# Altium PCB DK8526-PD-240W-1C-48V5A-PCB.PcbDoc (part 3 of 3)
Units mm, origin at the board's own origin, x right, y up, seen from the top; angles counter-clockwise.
Board outline 89.28 x 73.8 mm, 4 copper layers (Top Layer, Layer 1, Layer 2, Bottom Layer), stack 0.603 mm thick; 182 components, 162 nets, 518 pads, 506 vias.
Unrouted connection lines stored in the file: 4.
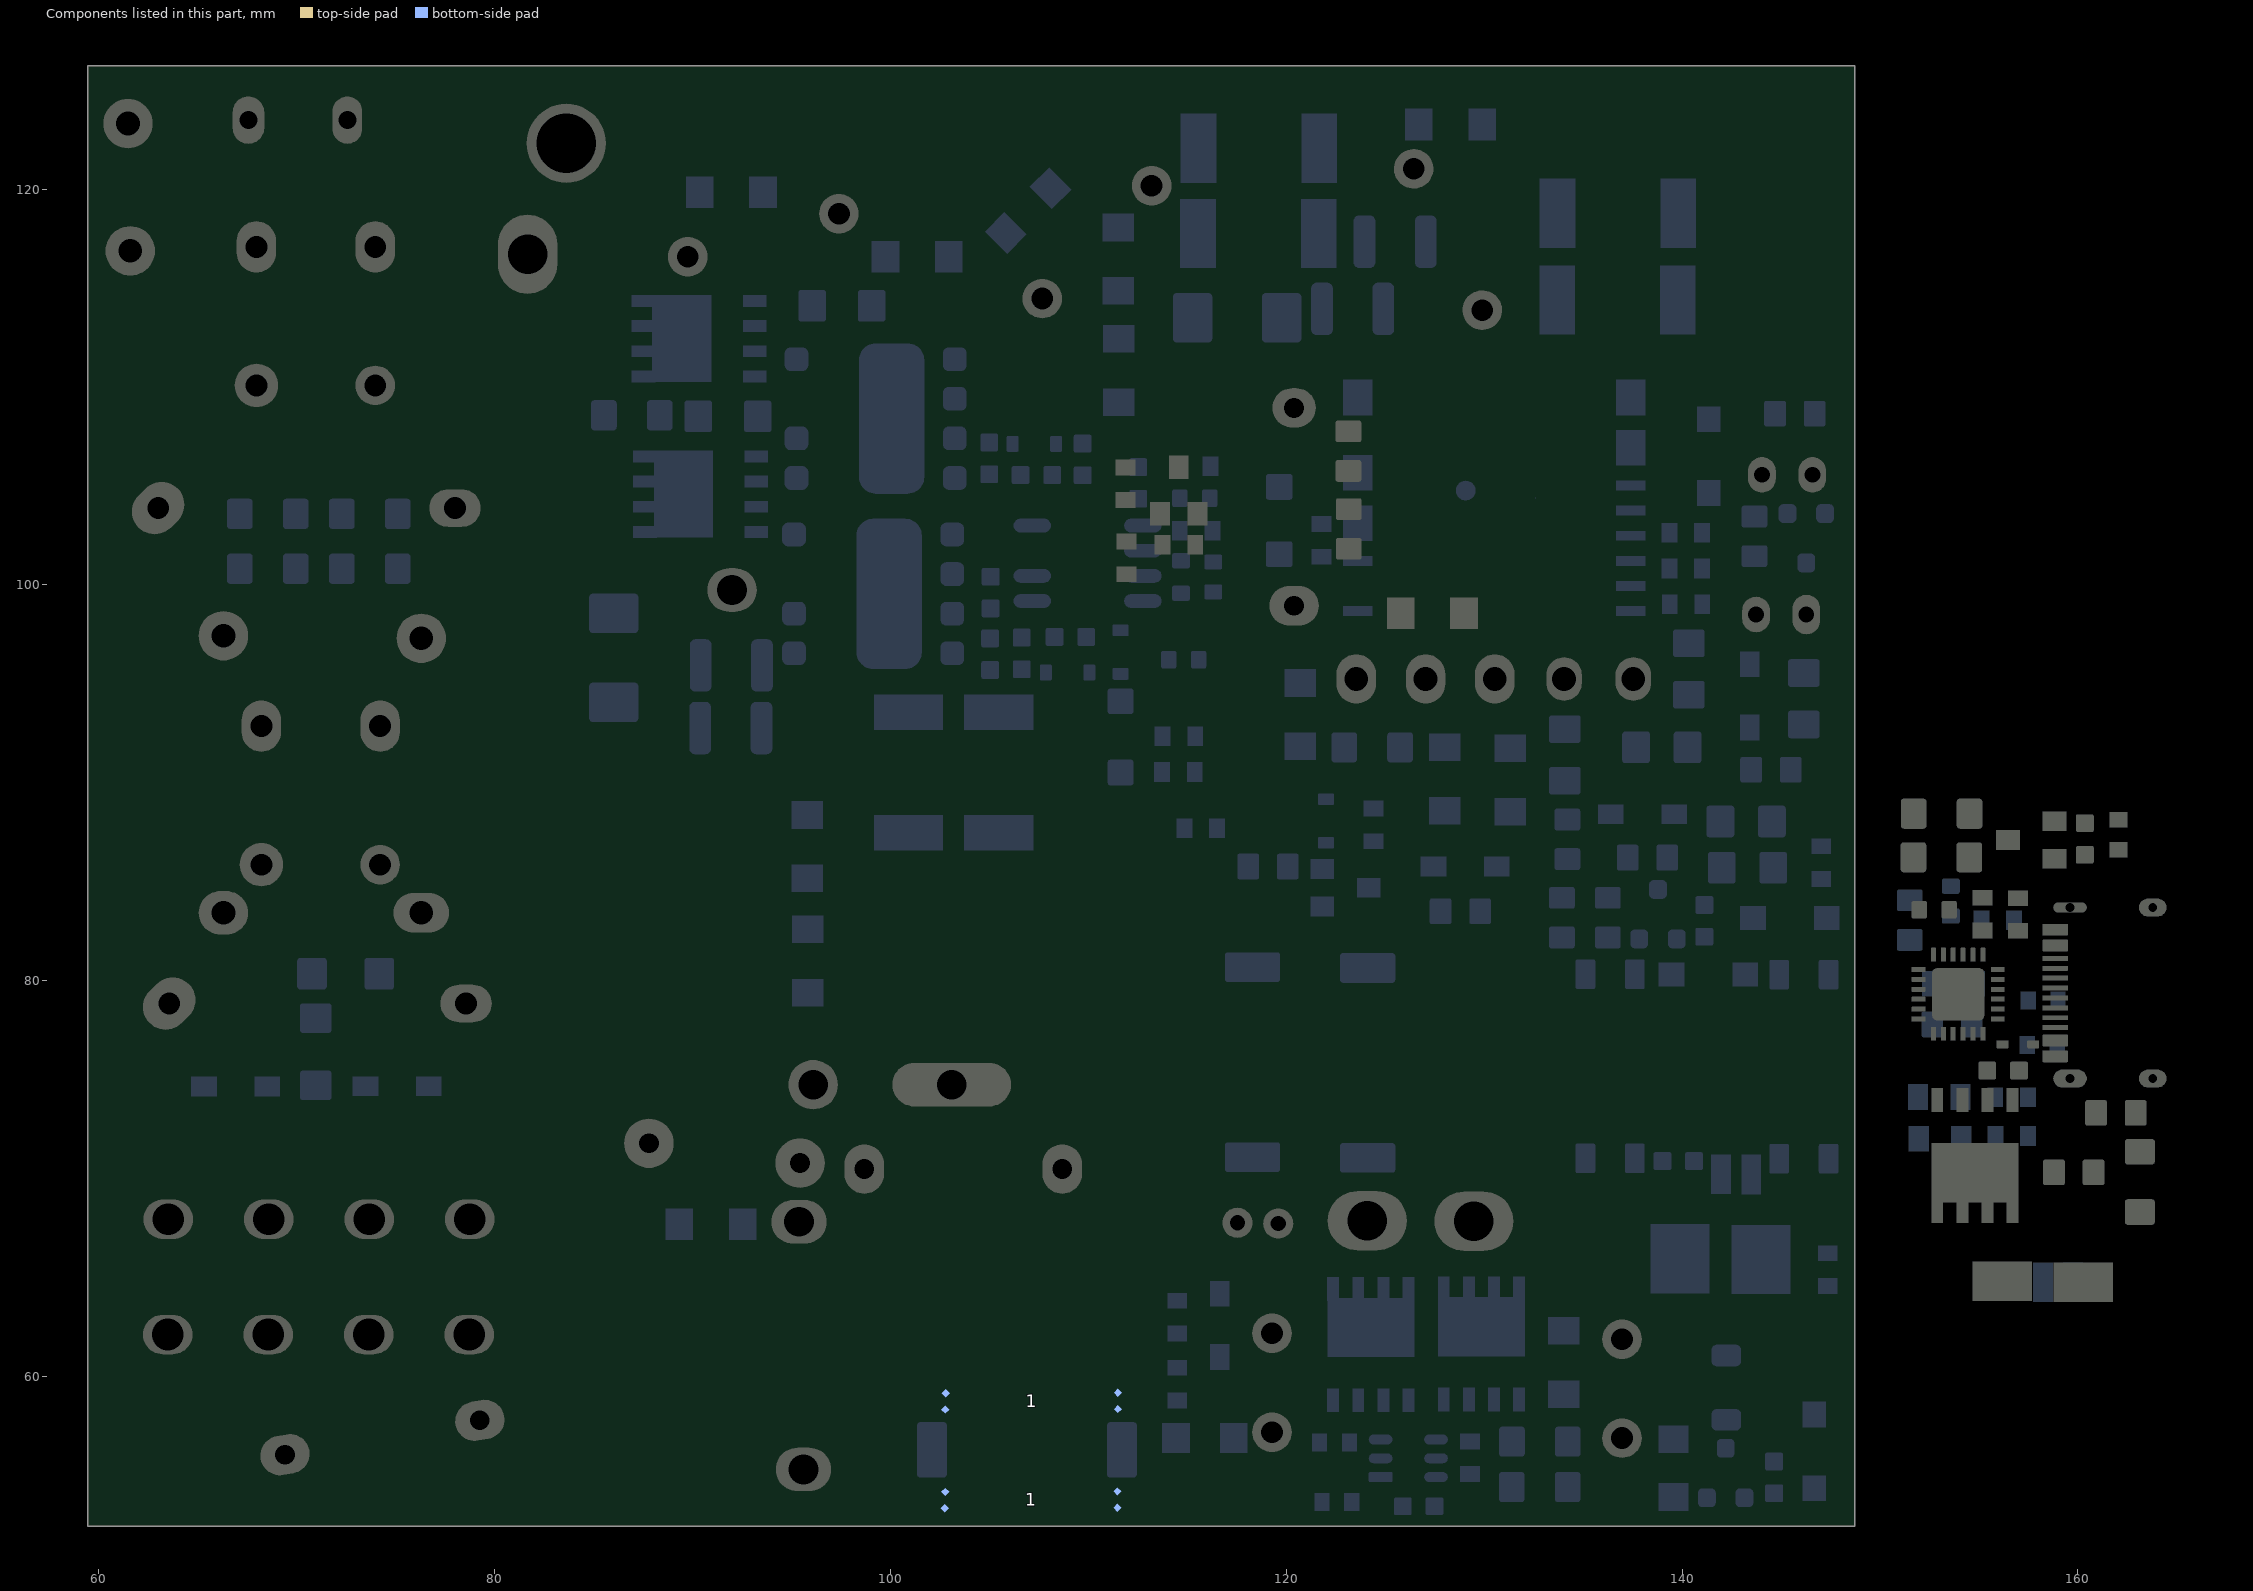
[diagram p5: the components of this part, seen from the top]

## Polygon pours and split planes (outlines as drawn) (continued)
300-R on Bottom Layer "NONET_L-01_P-001" (hatched Horizontal grid 0.2 track 0.2, pour order 442): 84.918,95.123 87.181,95.123 87.485,94.819 87.485,74.948 88.87,73.563 88.87,71.059 88.006,70.195 86.53,70.195 85.859,70.865 85.859,91.812 84.733,92.938 84.733,94.939
PGND on Bottom Layer "NONET_L-01_P-001" (hatched Horizontal grid 0.2 track 0.2, pour order 444): 131.773,107.101 131.773,111.059 132.039,111.325 135.577,111.325 136.506,112.254 136.58,112.18 136.58,109.136 135.732,108.288
PGND on Bottom Layer "NONET_L-01_P-001" (hatched Horizontal grid 0.2 track 0.2, pour order 449): 141.605,108.839 143.209,107.235 144.615,107.235 145.062,106.787 145.062,105.015 144.718,104.671 143.632,104.671 142.461,105.841 140.986,105.841
PGND on Bottom Layer "NONET_L-01_P-001" (hatched Horizontal grid 0.2 track 0.2, pour order 450): 147.955,99.568 146.027,99.568 145.571,99.112 145.571,97.988 146.026,97.533 147.907,97.533 148.109,97.735 148.109,99.414
GND on Bottom Layer "NONET_L-01_P-001" (hatched Horizontal grid 0.2 track 0.2, pour order 466): 92.583,89.281 89.67,89.281 89.133,88.744 89.133,77.315 90.039,76.409 91.961,76.409 92.937,77.385 92.937,88.927
PGND on Bottom Layer "NONET_L-01_P-001" (hatched Horizontal grid 0.2 track 0.2, pour order 470): 141.097,107.696 141.097,107.823 143.306,110.032 147.617,110.032 148.209,110.624 148.209,125.476 147.868,125.817 141.565,125.817 139.954,124.206 139.954,109.601
PGND on Bottom Layer "NONET_L-01_P-001" (hatched Horizontal grid 0.2 track 0.2, pour order 471): 18 vertices, not listed, extent 136.423,98.505 141.474,106.418
VS on Bottom Layer "NONET_L-01_P-001" (hatched Horizontal grid 0.2 track 0.2, pour order 477): 138.879,103.141 138.53,102.791 136.814,102.791 136.704,102.682 136.704,102.321 136.797,102.228 139.647,102.228 139.869,102.006 139.869,102.938 139.666,103.141
NetC22_2 on Bottom Layer "NONET_L-01_P-001" (hatched Horizontal grid 0.2 track 0.2, pour order 478): 136.719,101.075 136.716,101.079 136.716,101.416 136.844,101.544 139.473,101.544 139.662,101.355 139.662,100.377 139.618,100.333 139.113,100.333 138.504,100.941 136.821,100.941 136.718,101.044 136.718,101.077
VCC_EXT on Bottom Layer "NONET_L-01_P-001" (hatched Horizontal grid 0.2 track 0.2, pour order 479): 18 vertices, not listed, extent 136.661,98.452 139.704,100.314
GND on Bottom Layer "NONET_L-01_P-001" (hatched Horizontal grid 0.2 track 0.2, pour order 480): 85.181,125.766 85.598,125.349 85.598,117.856 82.423,114.681 80.899,114.681 80.01,115.57 80.01,125.086 80.69,125.766
d23 on Bottom Layer "NONET_L-01_P-001" (hatched Horizontal grid 0.2 track 0.2, pour order 481): 118.016,68.599 116.964,68.599 116.782,68.418 116.782,65.568 115.606,64.391 114.203,64.391 113.897,64.085 113.897,63.451 114.002,63.346 116.994,63.346 117.841,64.194 118.165,64.517 118.165,68.458 118.023,68.599
VCCF on Bottom Layer "NONET_L-01_P-001" (hatched Horizontal grid 0.2 track 0.2, pour order 482): 117.096,61.696 117.086,61.686 116.21,61.686 116.129,61.604 116.129,60.24 115.171,59.283 113.97,59.283 113.542,58.855 113.542,57.163 115.171,55.534 115.171,58.254 117.198,60.281 117.198,61.592 117.093,61.697
NetR60_2 on Bottom Layer "NONET_L-01_P-001" (hatched Horizontal grid 0.2 track 0.2, pour order 487): 125.288,55.079 124.174,55.079 123.338,54.243 122.955,54.243 122.784,54.072 122.784,53.312 123.005,53.09 124.002,53.09 124.176,53.264 124.176,53.907 124.794,54.525 125.226,54.525 125.379,54.679 125.379,54.988
VCCF on Bottom Layer "NONET_L-01_P-001" (hatched Horizontal grid 0.2 track 0.2, pour order 488): 115.025,55.893 116.853,54.066 122.112,54.066 122.215,53.963 122.215,53.296 122.048,53.129 117.559,53.129 114.982,55.706
NetR48_1 on Bottom Layer "NONET_L-01_P-001" (hatched Horizontal grid 0.2 track 0.2, pour order 489): 128.004,55.17 127.133,55.17 126.909,54.946 126.909,53.239 127.102,53.046 127.894,53.046 128.157,53.309 128.157,55.017 128,55.174
NetC26_1 on Bottom Layer "NONET_L-01_P-001" (hatched Horizontal grid 0.2 track 0.2, pour order 490): 126.118,54.102 124.957,54.102 124.593,53.739 124.594,53.243 124.822,53.014 126.21,53.014 126.425,53.228 126.425,53.796
NetC28_1 on Bottom Layer "NONET_L-01_P-001" (hatched Horizontal grid 0.2 track 0.2, pour order 491): 126.954,57.079 129.713,57.079 129.823,56.969 129.823,56.393 129.695,56.265 128.588,56.265 128.293,56.56 126.932,56.56 126.896,56.596 126.896,57.02
NetC26_1 on Bottom Layer "NONET_L-01_P-001" (hatched Horizontal grid 0.2 track 0.2, pour order 492): 128.329,69.401 134.232,69.401 135.04,68.594 135.04,61.564 134.422,60.946 122.253,60.946 122.153,61.045 122.153,65.015 122.378,65.239 125.725,65.239 127.254,66.769 127.254,68.326
NetC25_2 on Bottom Layer "NONET_L-01_P-001" (hatched Horizontal grid 0.2 track 0.2, pour order 493): 134.83,59.861 133.343,59.861 133.151,59.669 133.151,54.034 133.527,53.658 134.73,53.658 134.939,53.867 134.939,59.752
SGND on Bottom Layer "NONET_L-01_P-001" (hatched Horizontal grid 0.2 track 0.2, pour order 494): 34 vertices, not listed, extent 123.249,52.706 138.439,60.119
SGND on Bottom Layer "NONET_L-01_P-001" (hatched Horizontal grid 0.2 track 0.2, pour order 495): 121.516,57.569 121.532,57.585 121.532,59.404 121.894,59.767 123.046,59.767 123.409,59.404 123.878,59.874 124.396,59.874 124.396,60.112 120.297,60.112 120.083,59.898 120.083,58.795
SGND on Bottom Layer "NONET_L-01_P-001" (hatched Horizontal grid 0.2 track 0.2, pour order 499): 23 vertices, not listed, extent 115.688,54.626 125.318,60.104
pfcsw on Bottom Layer "NONET_L-01_P-001" (hatched Horizontal grid 0.2 track 0.2, pour order 515): 137.226,71.771 139.082,71.771 139.393,71.46 139.393,70.446 139.24,70.292 137.249,70.292 137.123,70.418 137.123,71.669
NetR73_2 on Bottom Layer "NONET_L-01_P-001" (hatched Horizontal grid 0.2 track 0.2, pour order 516): 140.225,71.438 142.245,71.438 142.483,71.2 142.483,69.274 142.395,69.187 141.495,69.187 140.132,70.55 140.132,71.344 140.232,71.444
NetR71_1 on Bottom Layer "NONET_L-01_P-001" (hatched Horizontal grid 0.2 track 0.2, pour order 517): 145.061,71.714 143.441,71.714 143.017,71.29 143.017,69.334 143.138,69.214 144.802,69.214 145.41,69.821 145.41,71.631 145.334,71.707
VOUT on Bottom Layer "NONET_L-01_P-001" (hatched Horizontal grid 0.2 track 0.2, pour order 518): 141.351,67.691 138.135,67.691 137.603,67.159 137.603,65.118 138.557,64.164 141.314,64.164 141.445,64.295 141.445,67.604 141.352,67.698
VOUT on Top Layer "NONET_L-01_P-001" (hatched Horizontal grid 0.2 track 0.2, pour order 506): 24 vertices, not listed, extent 117.486,60.057 141.351,69.373
GND on Top Layer "NONET_L-01_P-001" (hatched Horizontal grid 0.2 track 0.2, pour order 638): 17 vertices, not listed, extent 60.163,52.75 87.217,68.932
GND on Top Layer "NONET_L-01_P-001" (hatched Horizontal grid 0.2 track 0.2, pour order 624): 20 vertices, not listed, extent 99.822,73.584 120.039,92.786
GND on Top Layer "NONET_L-01_P-001" (hatched Horizontal grid 0.2 track 0.2, pour order 623): 109.605,72.767 103.123,72.767 102.743,72.387 102.743,69.469 103.378,68.834 108.696,68.834 109.831,69.969 109.831,72.541
GND on Top Layer "NONET_L-01_P-001" (hatched Horizontal grid 0.2 track 0.2, pour order 467): 83.995,114.76 86.027,114.76 86.357,114.427 86.357,98.623 91.38,93.599 108.966,93.599 109.893,92.672 109.893,78.905 108.712,77.724 85.113,77.724 83.763,79.074 83.763,114.528
GND on Top Layer "NONET_L-01_P-001" (hatched Horizontal grid 0.2 track 0.2, pour order 529): 23 vertices, not listed, extent 94.107,79.121 133.096,125.857
300V on Top Layer "NONET_L-01_P-001" (hatched Horizontal grid 0.2 track 0.2, pour order 619): 97.331,75.741 97.331,72.722 97.663,72.39 98.895,72.39 99.593,71.755 99.593,66.767 99.446,66.62 91.758,66.62 91.188,67.19 91.188,74.978 92.283,76.073 97,76.073
SGND on Top Layer "NONET_L-01_P-001" (hatched Horizontal grid 0.2 track 0.2, pour order 590): 159.258,67.945 159.132,68.071 159.132,68.708 159.91,69.486 159.91,71.078 160.134,71.302 161.193,71.302 161.804,70.691 161.804,69.53 162.558,68.777
VOUT on Top Layer "NONET_L-01_P-001" (hatched Horizontal grid 0.2 track 0.2, pour order 589): 156.464,71.755 157.447,71.755 158.04,71.162 159.149,71.162 159.363,70.947 159.363,69.8 157.762,68.199 156.972,68.199
NetC40_1 on Top Layer "NONET_L-01_P-001" (hatched Horizontal grid 0.2 track 0.2, pour order 567): 152.096,78.122 152.09,78.116 151.008,78.116 150.748,77.856 150.748,77.104 150.822,77.03 152.028,77.03 152.192,77.194 152.192,78.119
NetC37_1 on Top Layer "NONET_L-01_P-001" (hatched Horizontal grid 0.2 track 0.2, pour order 565): 151.713,81.434 151.705,81.442 150.869,81.442 150.764,81.337 150.764,80.8 151.02,80.543 152.196,80.543 152.219,80.567 152.219,80.932 151.709,81.442
SGND on Top Layer "NONET_L-01_P-001" (hatched Horizontal grid 0.2 track 0.2, pour order 564): 19 vertices, not listed, extent 150.698,77.969 155.285,84.377
c36 on Top Layer "NONET_L-01_P-001" (hatched Horizontal grid 0.2 track 0.2, pour order 562): 155.592,84.629 153.867,84.629 153.113,83.875 153.113,83.282 153.263,83.132 154.003,83.132 154.405,83.534 155.422,83.534 155.754,83.866 155.754,84.468 155.586,84.636
VOUT on Top Layer "NONET_L-01_P-001" (hatched Horizontal grid 0.2 track 0.2, pour order 559): 152.864,89.31 152.857,89.318 150.82,89.318 150.668,89.166 150.668,84.877 150.837,84.708 152.858,84.708 153.084,84.934 153.084,89.098 152.872,89.31
NetQ17_3 on Top Layer "NONET_L-01_P-001" (hatched Horizontal grid 0.2 track 0.2, pour order 558): 153.861,85.561 153.853,85.568 153.853,88.987 154.152,89.286 157.062,89.286 157.361,88.987 157.361,85.998 156.834,85.472 153.965,85.472 153.868,85.568
NetR66_1 on Top Layer "NONET_L-01_P-001" (hatched Horizontal grid 0.2 track 0.2, pour order 557): 163.441,89.063 163.433,89.056 161.749,89.056 161.538,88.845 161.538,87.773 161.737,87.574 163.478,87.574 163.791,87.887 163.791,88.711 163.445,89.058
SGND on Top Layer "NONET_L-01_P-001" (hatched Horizontal grid 0.2 track 0.2, pour order 556): 160.892,89.408 158.453,89.408 158.25,89.205 158.25,87.71 158.417,87.543 160.739,87.543 160.991,87.795 160.991,89.309
NetQ17_1 on Top Layer "NONET_L-01_P-001" (hatched Horizontal grid 0.2 track 0.2, pour order 555): 162.44,87.042 158.341,87.042 158.221,86.921 158.221,85.703 158.337,85.587 162.448,85.587 162.663,85.803 162.663,86.825 162.434,87.054
NetD16_1 on Top Layer "NONET_L-01_P-001" (hatched Horizontal grid 0.2 track 0.2, pour order 554): 21 vertices, not listed, extent 152.628,73.352 156.499,77.078
NetC32_2 on Top Layer "NONET_L-01_P-001" (hatched Horizontal grid 0.2 track 0.2, pour order 553): 157.828,72.608 161.508,72.608 161.671,72.771 161.671,74.422 161.259,74.01 160.593,74.01
SGND on Top Layer "NONET_L-01_P-001" (hatched Horizontal grid 0.2 track 0.2, pour order 544): 158.663,63.944 158.663,65.789 159.132,66.258 159.132,68.708 159.503,69.079 164.031,69.079 164.422,68.688 164.422,67.555 164.266,67.399 161.873,67.399 161.702,67.228 161.702,63.816 161.641,63.754 158.844,63.754 158.66,63.938
NetC32_2 on Top Layer "NONET_L-01_P-001" (hatched Horizontal grid 0.2 track 0.2, pour order 552): 21 vertices, not listed, extent 153.847,72.608 162.162,77.597
SGND2 on Top Layer "NONET_L-01_P-001" (hatched Horizontal grid 0.2 track 0.2, pour order 547): 17 vertices, not listed, extent 158.466,70.685 164.721,85.025
SGND2 on Top Layer "NONET_L-01_P-001" (hatched Horizontal grid 0.2 track 0.2, pour order 546): 158.733,76.351 158.755,76.373 159.632,76.373 160.629,75.376 160.629,74.708 160.465,74.543 158.875,74.543 158.369,75.049 158.369,76.121 158.541,76.293
VOUT on Top Layer "NONET_L-01_P-001" (hatched Horizontal grid 0.2 track 0.2, pour order 541): 154.723,63.903 154.73,63.91 154.73,67.208 154.507,67.431 150.787,67.431 150.594,67.623 150.594,71.446 150.94,71.792 157.409,71.792 157.688,71.514 157.688,66.446 157.688,63.944 157.534,63.79 154.842,63.79 154.729,63.903
SGND on Top Layer "NONET_L-01_P-001" (hatched Horizontal grid 0.2 track 0.2, pour order 532): 115.183,59.295 112.522,56.634 112.522,52.971 112.767,52.726 147.663,52.726 148.242,53.305 148.242,66.822 147.385,67.678 142.412,67.678 142.246,67.513 142.246,60.229 141.313,59.295
GND on Top Layer "NONET_L-01_P-001" (hatched Horizontal grid 0.2 track 0.2, pour order 530): 24 vertices, not listed, extent 116.556,79.448 148.158,117.471
no net on Top Layer "NONET_L-01_P-001" (solid, pour order 334): 132.019,81.044 132.019,79.543
XCD on Top Layer "NONET_L-01_P-001" (hatched Horizontal grid 0.2 track 0.2, pour order 388): 126.277,99.659 123.114,99.659 122.988,99.532 122.988,98.503 123.633,97.858 126.436,97.858 126.489,97.911 126.485,97.915 126.485,99.451
HV on Top Layer "NONET_L-01_P-001" (hatched Horizontal grid 0.2 track 0.2, pour order 389): 119.203,108.376 119.203,109.596 119.61,110.003 122.166,110.003 123.791,108.377 123.791,107.372 123.699,107.28 122.246,107.28 121.689,107.838 119.75,107.838 119.207,108.381
NetC2_1 on Top Layer "NONET_L-01_P-001" (hatched Horizontal grid 0.2 track 0.2, pour order 390): 123.698,102.362 121.917,102.362 119.114,99.559 119.114,98.486 119.607,97.993 121.037,97.993 121.58,98.535 121.58,100.792 122.135,101.347 123.725,101.347 123.777,101.399 123.777,102.283
PGND on Top Layer "NONET_L-01_P-001" (hatched Horizontal grid 0.2 track 0.2, pour order 391): 129.493,94.999 129.493,96.574 128.13,97.937 128.13,99.174 128.524,99.568 129.592,99.568 131.51,97.65 131.51,94.557 131.01,94.058 129.858,94.058 129.502,94.413
NetRS1_2 on Top Layer "NONET_L-01_P-001" (hatched Horizontal grid 0.2 track 0.2, pour order 457): 87.79,113.71 89.025,114.945 104.313,114.945 106.625,112.633 106.625,95.838 105.242,94.454 95.188,94.454 94.83,94.813 94.83,100.994 93.274,102.551 88.507,102.551 87.654,103.403
GND on Top Layer "NONET_L-01_P-001" (hatched Horizontal grid 0.2 track 0.2, pour order 460): 17 vertices, not listed, extent 80.132,114.554 98.459,125.574
PGND on Top Layer "NONET_L-01_P-001" (hatched Horizontal grid 0.2 track 0.2, pour order 475): 24 vertices, not listed, extent 125.72,94.058 148.126,125.857
NetC26_1 on Top Layer "NONET_L-01_P-001" (hatched Horizontal grid 0.2 track 0.2, pour order 504): 134.397,69.342 135.189,68.55 135.189,62.433 134.57,61.814 124.122,61.814 123.869,62.066 123.869,63.178 127.047,66.356 127.047,68.893 127.496,69.342
SGND on Top Layer "NONET_L-01_P-001" (hatched Horizontal grid 0.2 track 0.2, pour order 513): 142.246,67.515 142.246,60.229 141.313,59.295 117.74,59.295 116.314,57.869 116.314,52.662 142.07,52.662 145.669,56.261 145.669,67.461 145.443,67.687 145.434,67.678 142.412,67.678 142.254,67.52
no net on Top Overlay "NONET_L-01_P-001" (hatched Horizontal grid 0.2 track 0.2): 134.034,70.029 148.668,70.029 148.668,63.754 142.67,63.754 142.67,67.108 134.034,67.108
GND on Layer 2 "NONET_L01_P-001" (solid, remove dead copper, pour order 655): 20 vertices, not listed, extent 106.426,108.585 122.936,123.063
PGND on Layer 2 "NONET_L01_P-001" (solid, remove dead copper, pour order 654): 18 vertices, not listed, extent 111.252,82.461 131.953,110.871
GND on Layer 2 "NONET_L-01_P-001" (hatched Horizontal grid 0.2 track 0.2, pour order 447): 106.807,115.697 106.045,114.935 106.045,104.154 107.576,102.622 107.576,87.45 115.468,79.558 118.092,79.558 118.861,80.327 109.787,89.401 109.787,115.13 109.22,115.697
GND on Layer 2 "NONET_L-01_P-001" (hatched Horizontal grid 0.2 track 0.2, pour order 639): 64.529,69.075 60.82,69.075 60.126,68.381 60.126,53.674 60.919,52.881 90.053,52.881 90.352,53.18 90.352,54.684 89.964,55.072 77.83,55.072 74.049,58.853 66.15,58.853 65.078,59.925 65.078,68.526
NetBD1_1 on Layer 2 "NONET_L-01_P-001" (hatched Horizontal grid 0.2 track 0.2, pour order 636): 87.699,68.926 78.051,68.926 77.155,68.029 77.155,57.683 78.516,56.322 92.047,56.322 94.546,53.823 104.789,53.823 105.382,54.417 105.382,64.196 104.266,65.313 91.312,65.313
300V on Layer 2 "NONET_L-01_P-001" (hatched Horizontal grid 0.2 track 0.2, pour order 634): 97.848,75.75 97.848,73.221 99.593,71.476 99.593,67.237 98.865,66.509 91.748,66.509 90.814,67.443 90.814,74.803 92.065,76.054 97.544,76.054
NetBD1_2 on Layer 2 "NONET_L-01_P-001" (hatched Horizontal grid 0.2 track 0.2, pour order 629): 24 vertices, not listed, extent 72.465,61.099 80.518,87.183
NetBD1_3 on Layer 2 "NONET_L-01_P-001" (hatched Horizontal grid 0.2 track 0.2, pour order 627): 19 vertices, not listed, extent 60.715,61.044 70.21,87.168
NetCX1_1 on Layer 2 "NONET_L-01_P-001" (hatched Horizontal grid 0.2 track 0.2, pour order 615): 75.052,112.348 72.453,112.348 71.798,111.693 71.798,108.036 72.868,106.965 72.868,93.455 72.868,88.714 73.283,88.299 77.455,88.299 79.629,90.473 79.629,104.483 75.253,108.859 75.253,112.163 75.073,112.342
Y3 on Layer 2 "NONET_L-01_P-001" (hatched Horizontal grid 0.2 track 0.2, pour order 612): 71.999,124.758 71.894,124.653 71.894,113.653 72.353,113.194 74.586,113.194 75.025,113.633 75.025,124.735 74.792,124.968 72.205,124.968 71.985,124.748
NetF1_1 on Layer 2 "NONET_L-01_P-001" (hatched Horizontal grid 0.2 track 0.2, pour order 604): 60.071,122.301 60.071,125.073 60.571,125.572 67.926,125.572 68.444,125.054 68.444,122.462 67.872,121.89 60.495,121.89 60.074,122.311
NetLF2_1 on Layer 2 "NONET_L-01_P-001" (hatched Horizontal grid 0.2 track 0.2, pour order 599): 60.658,118.236 60.143,117.721 60.143,116.071 60.623,115.592 65.637,115.592 67.384,113.845 67.908,113.321 68.821,113.321 69.3,113.8 69.3,117.455 68.519,118.236
NetCX1_2 on Layer 2 "NONET_L-01_P-001" (hatched Horizontal grid 0.2 track 0.2, pour order 600): 68.952,112.382 68.939,112.395 62.869,112.395 60.89,110.416 60.89,90.124 62.718,88.297 68.451,88.297 69.406,89.253 69.406,93.742 69.282,93.866 69.282,106.954 69.282,112.086 68.972,112.397
SGND on Layer 2 "NONET_L-01_P-001" (hatched Horizontal grid 0.2 track 0.2, remove dead copper, pour order 584): 20 vertices, not listed, extent 150.783,66.675 164.716,89.354
VOUT on Layer 2 "NONET_L-01_P-001" (hatched Horizontal grid 0.2 track 0.2, pour order 583): 153.466,89.344 150.991,89.344 150.71,89.062 150.71,84.716 150.873,84.553 153.261,84.553 153.727,85.019 153.727,89.093 153.466,89.354
SGND2 on Layer 2 "NONET_L-01_P-001" (hatched Horizontal grid 0.2 track 0.2, pour order 582): 159.095,85.105 159.11,85.09 163.967,85.09 164.619,84.437 164.619,72.614 164.487,72.482 160.997,72.482 158.589,74.889 158.589,84.675 159.004,85.09
VOUT on Layer 2 "NONET_L-01_P-001" (hatched Horizontal grid 0.2 track 0.2, pour order 580): 152.049,74.479 153.93,74.479 157.831,70.578 157.831,67.845 157.473,67.487 151.129,67.487 150.732,67.883 150.732,71.643 151.552,72.462 151.552,73.985 152.049,74.482
SGND on Layer 2 "NONET_L-01_P-001" (hatched Horizontal grid 0.2 track 0.2, pour order 522): 118.618,59.309 117.754,59.309 115.62,61.443 115.62,68.048 117.866,70.294 121.534,70.294 121.998,70.758 121.998,71.702 121.747,71.953 117.169,71.953 112.077,66.861 112.077,53.198 112.45,52.825 120.832,52.825
GND on Layer 2 "NONET_L-01_P-001" (hatched Horizontal grid 0.2 track 0.2, pour order 451): 130.302,116.586 138.179,116.586 138.867,115.898 138.867,104.261 138.437,103.831 137.011,103.831 136.626,104.216 136.626,111.143 134.17,113.599 130.327,113.599 129.81,114.116 129.81,116.094
NetRS1_2 on Layer 2 "NONET_L-01_P-001" (hatched Horizontal grid 0.2 track 0.2, pour order 454): 103.91,115.32 92.386,115.32 90.297,113.232 90.297,104.521 98.92,95.898 103.528,95.898 104.521,96.891 104.521,114.71
PGND on Layer 2 "NONET_L-01_P-001" (hatched Horizontal grid 0.2 track 0.2, pour order 458): 23 vertices, not listed, extent 119.24,79.736 148.111,111.384
GND on Layer 2 "NONET_L-01_P-001" (hatched Horizontal grid 0.2 track 0.2, pour order 461): 38 vertices, not listed, extent 83.958,69.169 138.885,125.603
NetRS1_2 on Layer 2 "NONET_L-01_P-001" (hatched Horizontal grid 0.2 track 0.2, pour order 469): 94.488,100.838 94.488,95.615 95.231,94.872 105.28,94.872 106.383,95.975 106.383,100.989 104.677,102.695 103.299,102.695 101.854,104.14
PGND on Layer 2 "NONET_L-01_P-001" (hatched Horizontal grid 0.2 track 0.2, pour order 472): 148.054,125.854 139.951,125.854 139.415,125.318 139.415,108.997 141.633,106.779 148.029,106.779 148.153,106.903 148.128,106.928 148.128,125.854
NetC26_1 on Layer 2 "NONET_L-01_P-001" (hatched Horizontal grid 0.2 track 0.2, pour order 509): 128.752,69.661 133.158,69.661 134.078,68.741 134.078,62.069 133.91,61.901 124.035,61.901 123.869,62.066 123.869,63.178 127.047,66.356 127.047,68.893 127.824,69.669 128.681,69.669
VOUT on Layer 2 "NONET_L-01_P-001" (hatched Horizontal grid 0.2 track 0.2, pour order 510): 23 vertices, not listed, extent 117.92,60.057 141.351,69.622
VOUT on Layer 2 "NONET_L-01_P-001" (hatched Horizontal grid 0.2 track 0.2, pour order 511): 126.03,66.626 126.03,69.261 127.209,70.44 133.62,70.44 135.021,69.039 135.021,62.123 133.604,60.706 136.779,60.706 137.668,61.595 137.196,62.067 137.196,67.401 137.196,70.246 135.305,72.136 124.321,72.136 121.593,69.408
SGND on Layer 2 "NONET_L-01_P-001" (hatched Horizontal grid 0.2 track 0.2, pour order 512): 142.246,67.515 142.246,60.229 141.313,59.295 117.74,59.295 117.433,58.988 117.433,54.684 119.318,52.799 147.617,52.799 148.198,53.38 148.198,66.697 147.217,67.678 142.412,67.678 142.254,67.52
NetBD1_2 on Layer 1 "NONET_L-01_P-001" (hatched Horizontal grid 0.2 track 0.2, pour order 632): 79.93,79.709 80.201,79.438 80.201,74.286 75.114,69.198 75.114,61.738 74.396,61.02 72.554,61.02 72.242,61.332 72.242,78.312 73.638,79.709
GND on Layer 1 "NONET_L-01_P-001" (hatched Horizontal grid 0.2 track 0.2, pour order 640): 64.529,69.075 60.82,69.075 60.126,68.381 60.126,53.674 60.919,52.881 90.053,52.881 90.352,53.18 90.352,54.684 89.964,55.072 77.83,55.072 74.049,58.853 66.15,58.853 65.078,59.925 65.078,68.526
NetBD1_1 on Layer 1 "NONET_L-01_P-001" (hatched Horizontal grid 0.2 track 0.2, pour order 635): 87.726,69.119 78.079,69.119 77.183,68.222 77.183,57.876 78.544,56.515 92.075,56.515 94.574,54.016 104.816,54.016 105.41,54.61 105.41,64.389 104.293,65.506 91.339,65.506
300V on Layer 1 "NONET_L-01_P-001" (hatched Horizontal grid 0.2 track 0.2, pour order 620): 92.059,76.048 97.053,76.048 97.536,75.565 97.536,73.152 99.593,71.12 99.593,66.827 99.275,66.509 91.748,66.509 90.814,67.443 90.814,74.803
NetBD1_3 on Layer 1 "NONET_L-01_P-001" (hatched Horizontal grid 0.2 track 0.2, pour order 630): 17 vertices, not listed, extent 60.715,61.044 70.21,87.168
NetBD1_2 on Layer 1 "NONET_L-01_P-001" (hatched Horizontal grid 0.2 track 0.2, pour order 625): 78.854,86.994 78.817,86.956 73.085,86.956 72.22,86.092 72.22,83.355 73.152,82.423 78.994,82.423 79.557,82.986 79.557,86.291
NetLF2_1 on Layer 1 "NONET_L-01_P-001" (hatched Horizontal grid 0.2 track 0.2, pour order 337): 60.658,118.236 60.143,117.721 60.143,116.071 60.623,115.592 65.637,115.592 67.384,113.845 67.908,113.321 68.821,113.321 69.3,113.8 69.3,117.455 68.519,118.236
NetCX1_1 on Layer 1 "NONET_L-01_P-001" (hatched Horizontal grid 0.2 track 0.2, pour order 339): 75.052,112.348 72.453,112.348 71.798,111.693 71.798,107.6 72.868,106.53 72.868,93.316 72.868,88.714 73.283,88.299 77.455,88.299 79.629,90.473 79.629,104.313 75.253,108.689 75.253,112.163 75.073,112.342
NetCX1_2 on Layer 1 "NONET_L-01_P-001" (hatched Horizontal grid 0.2 track 0.2, pour order 338): 68.952,112.382 68.939,112.395 62.869,112.395 60.992,110.518 60.992,90.023 62.718,88.297 68.451,88.297 69.406,89.253 69.406,93.604 69.282,93.728 69.282,106.954 69.282,112.086 68.972,112.397
Y3 on Layer 1 "NONET_L-01_P-001" (hatched Horizontal grid 0.2 track 0.2, pour order 336): 71.999,124.758 71.894,124.653 71.894,113.653 72.353,113.194 74.586,113.194 75.025,113.633 75.025,124.735 74.792,124.968 72.205,124.968 71.985,124.748
NetF1_1 on Layer 1 "NONET_L-01_P-001" (hatched Horizontal grid 0.2 track 0.2, pour order 335): 60.071,122.301 60.071,125.073 60.571,125.572 67.926,125.572 68.444,125.054 68.444,122.462 67.872,121.89 60.495,121.89 60.074,122.311
SGND on Layer 1 "NONET_L-01_P-001" (hatched Horizontal grid 0.2 track 0.2, remove dead copper, pour order 585): 20 vertices, not listed, extent 150.679,66.9 164.665,89.435
VOUT on Layer 1 "NONET_L-01_P-001" (hatched Horizontal grid 0.2 track 0.2, pour order 581): 23 vertices, not listed, extent 150.777,67.842 162.433,89.154
VOUT on Layer 1 "NONET_L-01_P-001" (hatched Horizontal grid 0.2 track 0.2, pour order 579): 153.429,74.402 155.643,74.402 157.986,72.059 157.986,67.842 157.564,67.42 150.911,67.42 150.627,67.704 150.627,71.599 152.258,73.23
SGND on Layer 1 "NONET_L-01_P-001" (hatched Horizontal grid 0.2 track 0.2, pour order 521): 118.618,59.309 116.84,59.309 115.62,60.529 115.62,68.048 117.866,70.294 121.534,70.294 121.998,70.758 121.998,71.702 121.747,71.953 116.243,71.953 112.337,68.047 112.337,53.552 113.144,52.745 120.859,52.745
NetRS1_2 on Layer 1 "NONET_L-01_P-001" (hatched Horizontal grid 0.2 track 0.2, pour order 456): 103.91,115.32 91.124,115.32 89.35,113.547 89.35,105.468 98.816,96.002 102.969,96.002 104.521,97.554 104.521,114.71
PGND on Layer 1 "NONET_L-01_P-001" (hatched Horizontal grid 0.2 track 0.2, pour order 459): 26 vertices, not listed, extent 118.872,79.736 148.111,111.384
GND on Layer 1 "NONET_L-01_P-001" (hatched Horizontal grid 0.2 track 0.2, pour order 462): 116.459,92.075 102.087,92.075 90.244,80.232 90.244,78.56 91.294,77.509 98.573,77.509 101.861,74.221 101.861,69.462 102.616,68.707 108.462,68.707 117.327,77.572 117.327,84.592 117.327,91.157 116.474,92.011
GND on Layer 1 "NONET_L-01_P-001" (hatched Horizontal grid 0.2 track 0.2, pour order 463): 23 vertices, not listed, extent 83.92,87.582 135.672,125.857
GND on Layer 1 "NONET_L-01_P-001" (hatched Horizontal grid 0.2 track 0.2, pour order 465): 92.069,94.945 94.177,92.837 96.52,92.837 96.901,92.456 96.901,90.932 88.011,82.042 84.287,82.042 83.887,82.443 83.887,88.854
PGND on Layer 1 "NONET_L-01_P-001" (hatched Horizontal grid 0.2 track 0.2, pour order 473): 136.85,125.865 136.889,125.826 147.445,125.826 148.082,125.189 148.082,105.283 145.669,102.87 136.577,111.962 136.577,125.597 136.823,125.843
NetC26_1 on Layer 1 "NONET_L-01_P-001" (hatched Horizontal grid 0.2 track 0.2, pour order 501): 128.752,69.661 133.158,69.661 134.078,68.741 134.078,62.069 133.91,61.901 124.035,61.901 123.869,62.066 123.869,63.178 127.047,66.356 127.047,68.893 127.824,69.669 128.681,69.669
SGND on Layer 1 "NONET_L-01_P-001" (hatched Horizontal grid 0.2 track 0.2, pour order 502): 142.246,67.515 142.246,60.229 141.313,59.295 117.74,59.295 117.433,58.988 117.433,54.684 119.404,52.712 147.734,52.712 148.151,53.129 148.151,66.891 147.364,67.678 142.412,67.678 142.254,67.52
VOUT on Layer 1 "NONET_L-01_P-001" (hatched Horizontal grid 0.2 track 0.2, pour order 507): 23 vertices, not listed, extent 117.92,60.057 141.351,69.622
VOUT on Layer 1 "NONET_L-01_P-001" (hatched Horizontal grid 0.2 track 0.2, pour order 508): 126.03,66.626 126.03,69.261 127.209,70.44 133.62,70.44 135.021,69.039 135.021,62.123 133.604,60.706 136.779,60.706 137.668,61.595 137.21,62.053 137.21,70.181 135.255,72.136 124.321,72.136 121.593,69.408
no net on Bottom Solder "NONET_L01_P-001" (hatched Horizontal grid 0.1 track 0.1, remove dead copper): 129.921,110.998 126.492,110.998 126.111,110.617 126.111,107.569 124.968,106.426 124.968,102.997 126.238,101.727 126.238,97.409 126.619,97.028 127.635,97.028 127.889,97.282 127.889,101.727 130.302,104.14 130.302,110.617
no net on Bottom Solder "NONET_L01_P-001" (hatched Horizontal grid 0.1 track 0.1, remove dead copper): 132.207,111.252 131.826,110.871 131.826,102.87 129.794,100.838 129.794,97.409 130.175,97.028 132.334,97.028 133.223,97.917 135.509,97.917 135.763,98.171 135.763,105.41 136.271,105.918 136.271,111.125 136.144,111.252

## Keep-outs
Keep-Out Layer:
  circle w0.1: c162.027,67.038 r0.18
  circle w0.1: c154.419,67.046 r0.18
  circle w0.1: c146.113,67.884 r0.18
  circle w0.1: c146.115,69.019 r0.18
  circle w0.1: c137.711,67.9 r0.18
  circle w0.1: c137.711,69.017 r0.18
  circle w0.1: c160.119,76.491 r0.325
  circle w0.1: c160.11,82.251 r0.325
  lines w0.1: 137.711,68.157 137.711,67.9 137.728,67.884 146.113,67.884 146.118,67.889 146.118,69.016 146.112,69.022 137.706,69.022 137.711,69.017 137.711,68.167 ; 148.717,54.238 148.717,84.912 ; 148.717,126.229 148.717,52.434 59.436,52.434 59.436,126.238 114.427,126.238 148.717,126.238 ; 150.368,67.073 150.368,89.662 ; 154.439,63.573 154.439,67.073 ; 162.033,63.547 162.033,67.033 ; 150.368,89.662 150.368,67.09 150.385,67.073 ; 150.368,89.662 164.973,89.662 ; 150.368,89.662 164.973,89.662 ; 150.385,67.073 154.439,67.073 ; 150.385,67.073 154.439,67.073 ; 154.439,67.073 154.439,63.542 162.033,63.542 162.033,67.033 ; 162.033,67.033 162.027,67.038 164.955,67.038 164.973,67.056 164.973,89.662
  lines w1.2: 138.303,68.453 145.542,68.453

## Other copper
Top Layer:
  pour cut-out: 89.758,113.989 cw(c89.758,116.589) 87.158,116.589 cw(c89.758,116.589) 89.758,119.189 cw(c89.758,116.589) 92.358,116.589 cw(c89.758,116.589)
  pour cut-out: 126.412,118.561 cw(c126.412,121.161) 123.812,121.161 cw(c126.412,121.161) 126.412,123.761 cw(c126.412,121.161) 129.012,121.161 cw(c126.412,121.161)
  pour cut-out: 104.146,103.019 ccw(c105.776,103.019) 105.776,101.389 ccw(c105.776,103.019) 107.406,103.019 ccw(c105.776,103.019) 105.776,104.649 ccw(c105.776,103.019)
  pour cut-out: 143.753,95.931 cw(c143.753,98.531) 141.153,98.531 cw(c143.753,98.531) 143.753,101.131 cw(c143.753,98.531) 146.353,98.531 cw(c143.753,98.531)
  pour cut-out: 113.197,117.579 cw(c113.197,120.179) 110.597,120.179 cw(c113.197,120.179) 113.197,122.779 cw(c113.197,120.179) 115.797,120.179 cw(c113.197,120.179)
  pour cut-out: 116.426,107.32 111.701,107.32 110.621,106.239 110.621,98.067 111.357,97.331 116.426,97.331
  region net GND: 115.935,104.407 115.074,104.407 114.882,104.215 114.882,101.351 114.066,100.535 113.342,100.535 113.025,100.218 113.025,98.87 113.251,98.643 115.876,98.643 116.092,98.859 116.092,104.25
  region net NetQ12_1: 114.381,104.092 114.381,101.608 114.276,101.503 111.549,101.503 111.405,101.647 111.405,102.57 111.461,102.625 112.583,102.625 113.064,103.106 113.064,104.182 113.14,104.258 114.215,104.258
  region net NetQ12_3: 115.393,106.632 115.377,106.648 111.652,106.648 111.314,106.31 111.314,105.522 111.559,105.277 115.442,105.277 115.597,105.432 115.597,106.485 115.45,106.632
  region net NetC32_2: 158.223,81.867 158.223,82.091 159.631,82.091 159.874,81.848 161.607,81.848 162.287,81.168 162.287,76.734 162.119,76.566 160.756,76.566 160.441,76.881 159.911,76.881 159.699,76.669 158.076,76.669 157.861,76.454 157.861,73.316 154.936,73.316 154.873,73.38 154.873,74.441 155.023,74.592 155.789,74.592 156.236,75.039 156.236,75.886 156.891,76.541 156.891,77.098 157.129,77.336 159.728,77.336 160.569,78.177 160.569,80.074 159.907,80.735 159.907,81.217 159.675,81.449 158.641,81.449
Layer 1:
  pour cut-out: 98.573,77.509 106.006,77.509 107.061,76.454 107.061,73.66 106.172,72.771 102.79,72.771 101.861,71.842 98.425,75.277 98.425,77.216
  pour cut-out: 112.353,100.234 ccw(c113.983,100.234) 113.983,98.604 ccw(c113.983,100.234) 115.613,100.234 ccw(c113.983,100.234) 113.983,101.864 ccw(c113.983,100.234)
  pour cut-out: 88.117,116.587 ccw(c89.747,116.587) 89.747,114.957 ccw(c89.747,116.587) 91.378,116.587 ccw(c89.747,116.587) 89.747,118.218 ccw(c89.747,116.587)
  pour cut-out: 142.112,98.507 ccw(c143.742,98.507) 143.742,96.877 ccw(c143.742,98.507) 145.372,98.507 ccw(c143.742,98.507) 143.742,100.137 ccw(c143.742,98.507)
  pour cut-out: 142.112,98.504 ccw(c143.743,98.504) 143.743,96.873 ccw(c143.743,98.504) 145.373,98.504 ccw(c143.743,98.504) 143.743,100.134 ccw(c143.743,98.504)
  pour cut-out: 118.765,108.951 ccw(c120.396,108.951) 120.396,107.321 ccw(c120.396,108.951) 122.026,108.951 ccw(c120.396,108.951) 120.396,110.581 ccw(c120.396,108.951)
  pour cut-out: 111.567,120.179 ccw(c113.197,120.179) 113.197,118.549 ccw(c113.197,120.179) 114.827,120.179 ccw(c113.197,120.179) 113.197,121.81 ccw(c113.197,120.179)
  pour cut-out: 124.862,121.137 ccw(c126.492,121.137) 126.492,119.507 ccw(c126.492,121.137) 128.122,121.137 ccw(c126.492,121.137) 126.492,122.767 ccw(c126.492,121.137)
  pour cut-out: 124.862,121.137 ccw(c126.492,121.137) 126.492,119.507 ccw(c126.492,121.137) 128.122,121.137 ccw(c126.492,121.137) 126.492,122.767 ccw(c126.492,121.137)
  pour cut-out: 135.911,95.25 ccw(c137.541,95.25) 137.541,93.62 ccw(c137.541,95.25) 139.171,95.25 ccw(c137.541,95.25) 137.541,96.88 ccw(c137.541,95.25)
  pour cut-out: 118.766,98.951 ccw(c120.396,98.951) 120.396,97.321 ccw(c120.396,98.951) 122.026,98.951 ccw(c120.396,98.951) 120.396,100.581 ccw(c120.396,98.951)
  pour cut-out: 132.411,95.25 ccw(c134.041,95.25) 134.041,93.62 ccw(c134.041,95.25) 135.671,95.25 ccw(c134.041,95.25) 134.041,96.88 ccw(c134.041,95.25)
  pour cut-out: 81.409,70.711 81.719,70.401 81.719,60.116 82.072,59.764 82.744,59.764 83.077,60.097 83.077,70.842
  pour cut-out: 162.605,69.406 162.605,70.47 162.776,70.642 163.367,70.642 163.491,70.518 163.491,69.193 163.338,69.04 162.735,69.04 162.617,69.158
  pour cut-out: 154.178,82.804 154.305,82.677 154.305,82.169 154.051,81.915 152.908,81.915 152.781,82.042 152.781,82.677 152.908,82.804
Layer 2:
  pour cut-out: 111.591,120.09 ccw(c113.221,120.09) 113.221,118.46 ccw(c113.221,120.09) 114.851,120.09 ccw(c113.221,120.09) 113.221,121.72 ccw(c113.221,120.09)
  pour cut-out: 132.411,95.25 ccw(c134.041,95.25) 134.041,93.62 ccw(c134.041,95.25) 135.671,95.25 ccw(c134.041,95.25) 134.041,96.88 ccw(c134.041,95.25)
  pour cut-out: 135.911,95.25 ccw(c137.541,95.25) 137.541,93.62 ccw(c137.541,95.25) 139.171,95.25 ccw(c137.541,95.25) 137.541,96.88 ccw(c137.541,95.25)
  pour cut-out: 88.175,116.603 ccw(c89.805,116.603) 89.805,114.973 ccw(c89.805,116.603) 91.435,116.603 ccw(c89.805,116.603) 89.805,118.233 ccw(c89.805,116.603)
  pour cut-out: 142.112,98.507 ccw(c143.742,98.507) 143.742,96.877 ccw(c143.742,98.507) 145.372,98.507 ccw(c143.742,98.507) 143.742,100.137 ccw(c143.742,98.507)
  pour cut-out: 124.926,121.106 ccw(c126.556,121.106) 126.556,119.476 ccw(c126.556,121.106) 128.186,121.106 ccw(c126.556,121.106) 126.556,122.736 ccw(c126.556,121.106)
  pour cut-out: 81.318,70.078 81.628,69.768 81.628,59.484 81.981,59.131 82.653,59.131 82.986,59.464 82.986,70.209
  pour cut-out: 162.814,70.612 163.308,70.612 163.409,70.511 163.409,69.274 163.324,69.189 162.829,69.189 162.724,69.295 162.732,69.303 162.732,70.519 162.813,70.6
  pour cut-out: 154.178,82.804 154.305,82.677 154.305,82.169 154.051,81.915 152.908,81.915 152.781,82.042 152.781,82.677 152.908,82.804
Bottom Layer:
  region net SGND: 111.304,59.534 111.32,59.55 112.695,59.55 113.067,59.178 113.067,53.631 112.219,52.783 111.201,52.783 110.917,53.067 110.917,59.118 111.221,59.423
  region net NetBD1_1: 102.896,59.506 102.098,59.506 100.252,57.661 94.747,57.661 93.969,56.883 93.969,52.993 94.311,52.651 102.775,52.651 102.94,52.816 102.94,59.463
  pour cut-out: 152.755,82.179 152.764,82.188 152.764,85.001 153.06,85.298 154.543,85.298 156.143,83.698 157.132,83.698 159.055,81.775 160.816,81.775 162.433,80.158 162.433,71.501 163.449,70.485 163.449,69.215 163.195,68.961 162.56,68.961 161.036,70.485 161.036,79.506 159.828,80.714 158.399,80.714 157.716,81.397 153.385,81.397 152.75,82.032 152.75,82.172

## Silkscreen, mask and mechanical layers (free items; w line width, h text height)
Top Overlay:
  drawing of 3913 lines, arcs and shapes, not listed
  text "HS" at 78.613,119.412 h3
  text "T+" at 120.904,69.088 h2
  text "TA" at 116.459,68.834 h1.52
  text "TB" at 118.745,68.834 h1.52
  text "T-" at 131.699,68.58 h2
Bottom Overlay:
  drawing of 1949 lines, arcs and shapes, not listed
  text "OPTO" at 146.856,69.275 h0.7
  text "PFC" at 140.308,69.19 h0.7
  text "OUT+" at 140.927,63.157 h0.7
  text "PGND" at 144.897,63.157 h0.7

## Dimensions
162.033,63.542 to 164.973,89.662 on Top Overlay
150.368,67.073 to 164.973,67.056 on Top Overlay
59.436,52.434 to 59.436,126.238 on Top Overlay
148.717,52.434 to 59.436,52.434 on Top Overlay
